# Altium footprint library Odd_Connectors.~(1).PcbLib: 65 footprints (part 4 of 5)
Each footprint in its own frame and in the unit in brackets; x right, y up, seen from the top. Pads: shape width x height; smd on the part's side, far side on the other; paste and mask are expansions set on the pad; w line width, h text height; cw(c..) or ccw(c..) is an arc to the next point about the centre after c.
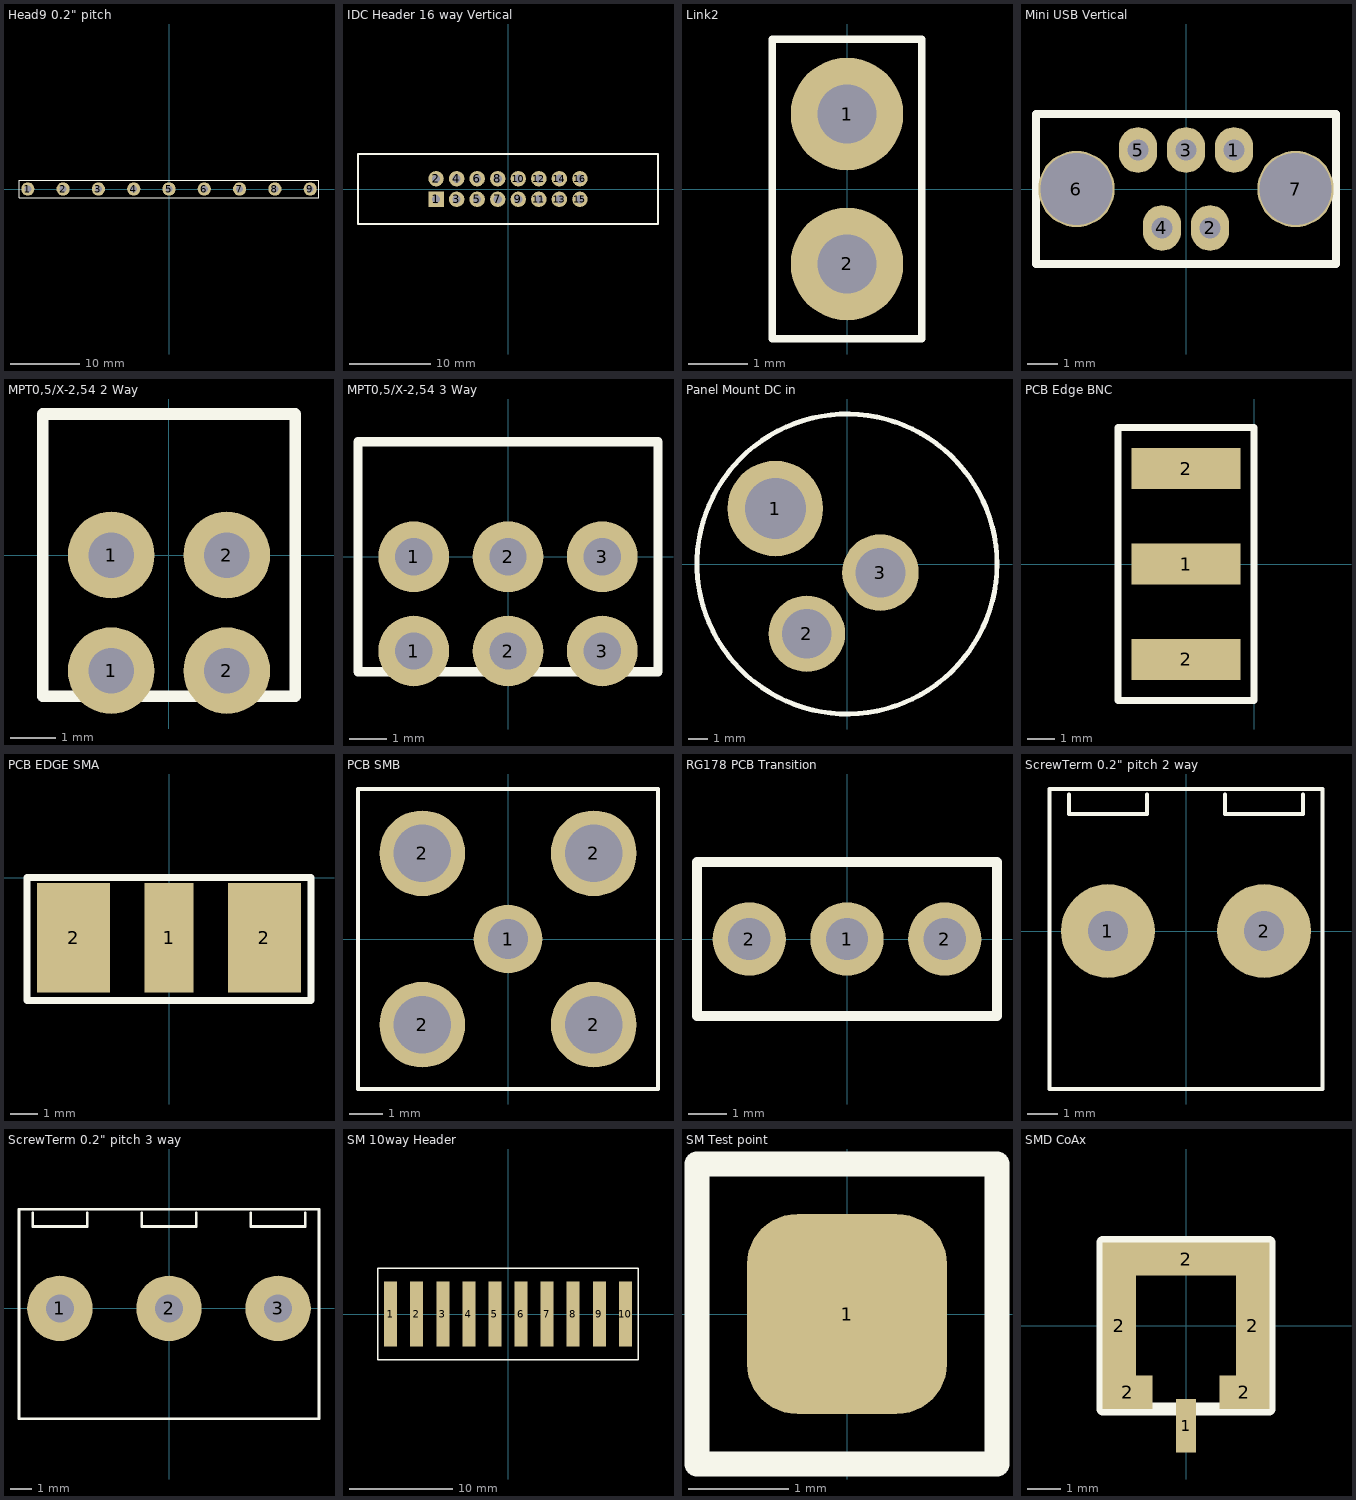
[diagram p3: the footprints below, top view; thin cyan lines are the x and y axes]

## Head9 0.2" pitch [mm] "9 way header on 0.2\" pitch"
height 12.7
pads (9):
  round 1.905 hole 1: 1(-20.32,0) 2(-15.24,0) 3(-10.16,0) 4(-5.08,0) 5(0,0) 6(5.08,0) 7(10.16,0) 8(15.24,0) 9(20.32,0)
Top Overlay:
  lines w0.127: -21.59,-1.27 -21.59,1.27 21.59,1.27 21.59,-1.27 -21.59,-1.27

## IDC Header 16 way Vertical [mm] "IDC Header 16 way Vertical"
height 20
pads (16):
  rect 1.905x1.905 hole 1: 1(-8.89,-1.27)
  round 1.905 hole 1: 2(-8.89,1.27) 3(-6.35,-1.27) 4(-6.35,1.27) 5(-3.81,-1.27) 6(-3.81,1.27) 7(-1.27,-1.27) 8(-1.27,1.27) 9(1.27,-1.27) 10(1.27,1.27) 11(3.81,-1.27) 12(3.81,1.27) 13(6.35,-1.27) 14(6.35,1.27) 15(8.89,-1.27) 16(8.89,1.27)
Top Overlay:
  lines w0.254: -18.542,-4.318 -18.542,4.318 18.542,4.318 18.542,-4.318 -18.542,-4.318

## Link2 [mm] "2 pin link"
height 12
pads (2):
  round 1.905 hole 1: 1(0,1.27) 2(0,-1.27)
Top Overlay:
  lines w0.127: -1.27,-2.54 -1.27,2.54 1.27,2.54 1.27,-2.54 -1.27,-2.54

## Mini USB Vertical [mm]
pads (7):
  oval 1.27x1.524 hole 0.7: 1(1.6,1.3) 2(0.8,-1.3) 3(0,1.3) 4(-0.8,-1.3) 5(-1.6,1.3)
  round 2.54 hole 2.4: 6(-3.65,0) 7(3.65,0)
Top Overlay:
  lines w0.254: -5,-2.5 -5,2.5 5,2.5 5,-2.5 -5,-2.5

## MPT0,5/X-2,54 2 Way [mm] "0.1\" pitch screw terminals"
height 5.08
pads (4):
  round 1.905 hole 1: 1(-1.27,-2.54) 1(-1.27,0) 2(1.27,-2.54) 2(1.27,0)
Top Overlay:
  lines w0.254: -2.77,-3.1 2.77,-3.1 2.77,3.1 -2.77,3.1 -2.77,-3.1

## MPT0,5/X-2,54 3 Way [mm] "0.1\" pitch screw terminals"
height 5.08
pads (6):
  round 1.905 hole 1: 1(-2.54,-2.54) 1(-2.54,0) 2(0,-2.54) 2(0,0) 3(2.54,-2.54) 3(2.54,0)
Top Overlay:
  lines w0.254: -4.04,-3.1 4.04,-3.1 4.04,3.1 -4.04,3.1 -4.04,-3.1

## Panel Mount DC in [mm] "Panel Mount DC in mounted horiz on PCB"
pads (3):
  round 5 hole 3.2: 1(-3.75,2.9)
  round 4 hole 2.6: 2(-2.1,-3.65) 3(1.75,-0.45)
Top Overlay:
  circle w0.254: c0,0 r7.85

## PCB Edge BNC [mm]
pads (3):
  rect 4x1.5 smd: 1(-2.5,0) 2(-2.5,-3.5) 2(-2.5,3.5)
Top Overlay:
  lines w0.254: -5,-5 -5,5 0,5 0,-5 -5,-5

## PCB EDGE SMA [mm] "Edge launch SMA such as Molex 73251-2120"
pads (3):
  rect 1.78x4 smd: 1(0,-2.2)
  rect 2.665x4 smd: 2(-3.492,-2.2) 2(3.492,-2.2)
Top Overlay:
  lines w0.254: -5.2,-4.5 -5.2,0 5.2,0 5.2,-4.5 -5.2,-4.5

## PCB SMB [mm] "PCB mount SMB connector"
height 15
pads (5):
  round 2.032 hole 1.2: 1(0,0)
  round 2.54 hole 1.7: 2(-2.54,-2.54) 2(-2.54,2.54) 2(2.54,-2.54) 2(2.54,2.54)
Top Overlay:
  lines w0.127: -4.445,-4.445 4.445,-4.445 4.445,4.445 -4.445,4.445 -4.445,-4.445

## RG178 PCB Transition [mm] "Connect coax to pcb"
height 10
pads (3):
  round 1.905 hole 1.1: 1(0,0) 2(-2.54,0) 2(2.54,0)
Top Overlay:
  lines w0.254: -3.9,-2 -3.9,2 3.9,2 3.9,-2 -3.9,-2

## ScrewTerm 0.2" pitch 2 way [mil] "PCB mounted screw terminal 0.2\" pitch  Camden"
height 551.18
pads (2):
  round 120 hole 51.18: 1(-100,0) 2(100,0)
Top Overlay:
  lines w5: -150,175 -150,150 -50,150 -50,175 ; 50,175 50,150 150,150 150,175 ; -175,-202.5 175,-202.5 175,182 -175,182 -175,-202.5

## ScrewTerm 0.2" pitch 3 way [mil] "PCB mounted screw terminal 0.2\" pitch  Camden"
height 551.18
pads (3):
  round 120 hole 51.18: 1(-200,0) 2(0,0) 3(200,0)
Top Overlay:
  lines w5: -250,175 -250,150 -150,150 -150,175 ; -50,175 -50,150 50,150 50,175 ; 150,175 150,150 250,150 250,175 ; -275,-202.5 -275,182 275,182 275,-202.5 -275,-202.5

## SM 10way Header [mil] "SM 10 way header 0.1\" pitch"
height 401.57
pads (10):
  rect 50x250 smd: 1(-450,0) 2(-350,0) 3(-250,0) 4(-150,0) 5(-50,0) 6(50,0) 7(150,0) 8(250,0) 9(350,0) 10(450,0)
Top Overlay:
  lines w5: -500,-175 -500,175 500,175 500,-175 -500,-175

## SM Test point [mm] "SM Test point 100 x 100mil"
pads (1):
  rrect50% 2x2 smd: 1(0,0)
Top Overlay:
  lines w0.254: -1.5,-1.5 -1.5,1.5 1.5,1.5 1.5,-1.5 -1.5,-1.5

## SMD CoAx [mm] "MIL-STD-348 sm coax"
height 4.1
pads (6):
  rect 0.6x1.6 smd: 1(0,-3)
  rect 1x5 smd: 2(-2,0) 2(2,0)
  rect 1.5x1 smd: 2(-1.75,-2) 2(1.75,-2)
  rect 5x1 smd: 2(0,2)
Top Overlay:
  lines w0.381: -2.5,-2.5 2.5,-2.5 2.5,2.5 -2.5,2.5 -2.5,-2.5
